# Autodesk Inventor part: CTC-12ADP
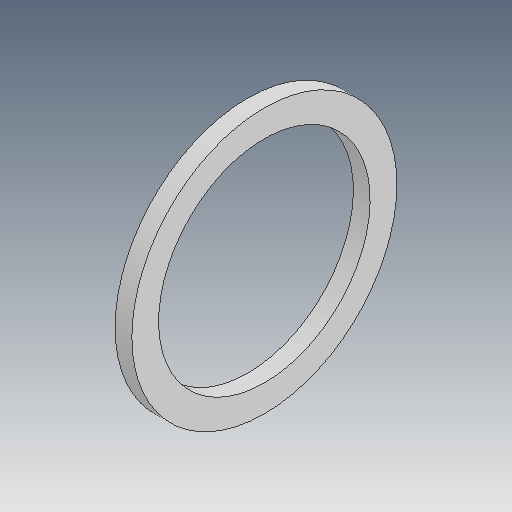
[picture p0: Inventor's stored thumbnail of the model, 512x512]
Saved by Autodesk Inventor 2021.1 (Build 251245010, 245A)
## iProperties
Created: 2010-01
Part Number: CTC-12ADP
Material: Ogólny
Document SubType Name: Modeling
Designer: user
Density: 1 g/cm^3
Appearance: Domyślna
Author: user
Revision Number: 1LAST_VERSION
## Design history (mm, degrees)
feature "Baza1"
node "Bryła1"
